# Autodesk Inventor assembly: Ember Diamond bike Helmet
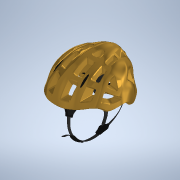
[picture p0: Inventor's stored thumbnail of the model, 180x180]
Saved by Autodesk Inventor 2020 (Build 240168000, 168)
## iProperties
Created: 2021-04
Part Number: Ember Diamond bike Helmet
Document SubType Name: Assembly
Designer: bruno
Title: C:/Users/admin/Downloads/Ember Diamond bike Helmet.step
Sending System: Autodesk Translation Framework v10.6.0.1341
Preprocessor: ST-DEVELOPER v18.1
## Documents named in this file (5)
- C:\Users\bruno\Downloads\ember-diamond-bike-helmet-1.snapshot.1\Ember Diamond bike Helmet.iam
- C:\Users\bruno\Downloads\ember-diamond-bike-helmet-1.snapshot.1\Helmet shell.ipt
- C:\Users\bruno\Downloads\ember-diamond-bike-helmet-1.snapshot.1\Strap.iam
- C:\Users\bruno\Downloads\ember-diamond-bike-helmet-1.snapshot.1\Strap holder Front.ipt
- C:\Users\bruno\Downloads\ember-diamond-bike-helmet-1.snapshot.1\Rear Lock.ipt
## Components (4 placed, 4 different names)
1. Helmet shell:1
2. Strap:1 [sub-assembly]
3. Strap holder Front:2
4. Rear Lock:1
